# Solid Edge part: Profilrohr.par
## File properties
Username: bmolnar
Dokumentum tartalom típus: 0
Author: bmolnar
Last saved by: bmolnar
Revision: 91
Sűrűség: 0,000 kg/m^3
Pontosság: 0,990
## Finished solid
Body 1: solid body, 91 faces, 266 edges, 176 vertices.
  Faces by surface: plane 46, cylinder 45
  Edges by curve: line 176, circle 90
Bounding box of the edges (mm): 49.000 x 49.000 x 175.800, from (-24.5, -24.5, 0) to (24.5, 24.5, 175.8).
Cylindrical faces by radius (mm): R0.15 x20, R0.25 x20, R8 x4, R16 x1
Planar faces by outward normal: +x 11, +y 11, +z 1, -x 11, -y 11, -z 1
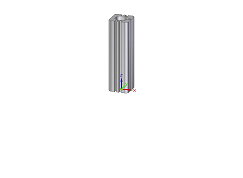
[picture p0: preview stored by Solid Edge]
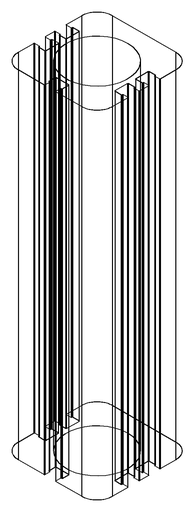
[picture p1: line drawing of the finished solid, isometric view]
